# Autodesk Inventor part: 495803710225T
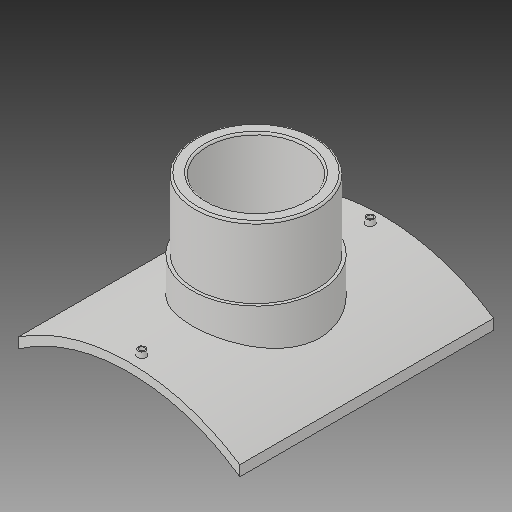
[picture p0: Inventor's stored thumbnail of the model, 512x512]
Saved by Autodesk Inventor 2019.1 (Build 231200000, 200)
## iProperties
Created: 2017-10
Part Number: 495803710225T
Material: Generic
Description: PLASSON BRANCH SADDLE  710x225
Document SubType Name: Modeling
Designer: KIM
Mass: 2754.05 g
Surface Area: 3037.44 cm^2
Volume: 2754.05 cm^3
Density: 1 g/cm^3
Appearance: Default
Author: KIM
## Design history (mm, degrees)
derived "495803.ipt"
feature "Solid1::495803.ipt"
tag "TaggingFeature1"
body "Solid1"
other parameters: "d1" = 16, "d4" = 0, "d12" = 380.6, "d13" = 14, "d14" = 211.5, "d16" = 5 deg, "d18" = 4, "d19" = 14, "d20" = 0, "d21" = 3, "d22" = 0, "d23" = 558, "d24" = 236.25, "d25" = 16, "d28" = 0, "d29" = 9.6, "d31" = 0, "d32" = 93.5, "d33" = 0, "d34" = 7.1, "d36" = 225, "d37" = 130.9, "d38" = 0, "d39" = 3.55, "d_1" = 225, "H_" = 187, "x_" = 16, "D_" = 16
